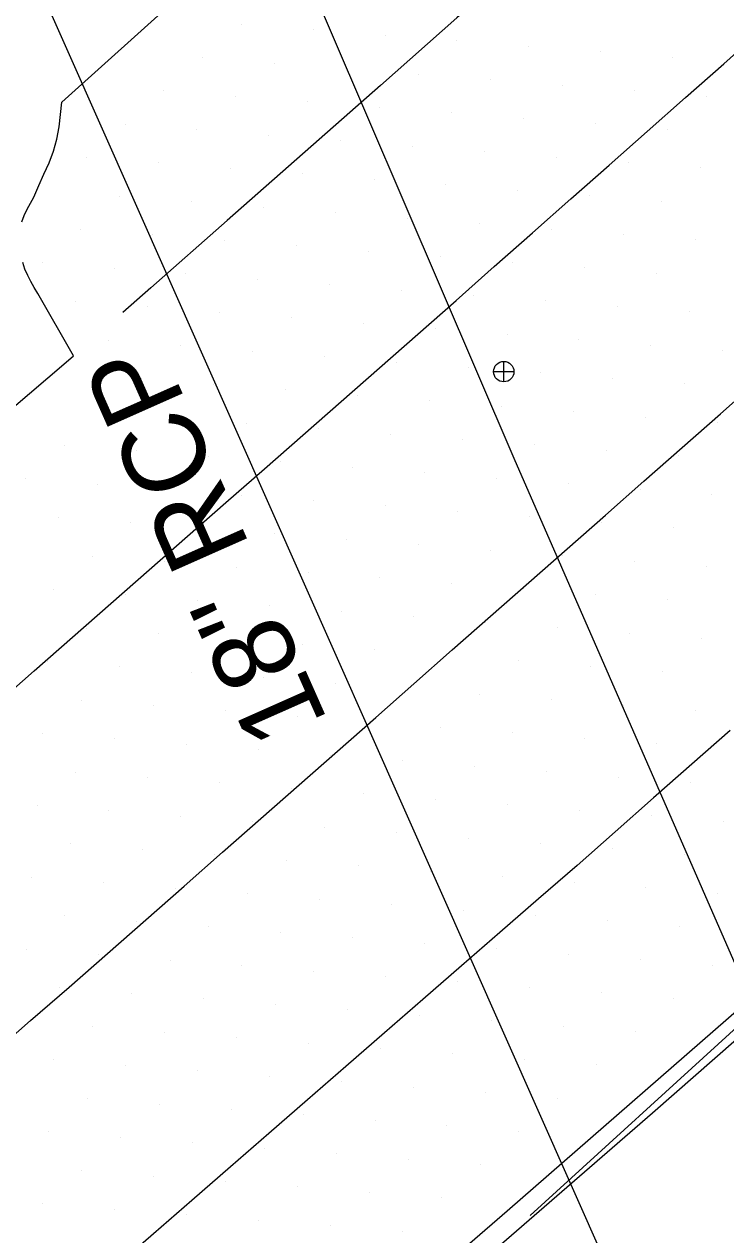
# Model space of a CAD drawing. Extents: x 1548934 to 1561348, y 809680 to 824075.
# Drawn here: x 1551806.2 to 1551840.5, y 810646.5 to 810705.8 of the extents above; entities that cross this region are included whole.
import ezdxf

# ---------------------------------------------------------------- set-up
doc = ezdxf.new("R2010")
doc.units = 0
for name, color, linetype in [('Default', 7, 'Continuous'), ('E_NCDOT_Vertical_Profile_Ground_Line', 7, 'Continuous'), ('Exist DTM Scan Elevation Point', 7, 'Continuous'), ('Exist Guardrail', 7, 'Continuous'), ('Exist Structure Major Deck Tunnel Box Culvert', 7, 'Continuous'), ('Exist Structure Minor Pipes RCP 18 Inch Size Material Text', 7, 'Continuous'), ('P_RDY_Terminator_Cell', 7, 'Continuous'), ('Pattern_8', 7, 'Continuous'), ('PH Exist DTM Breakline', 7, 'Continuous')]:
    doc.layers.add(name, color=color, linetype=linetype)

# ---------------------------------------------------------------- blocks, each defined once
blk = doc.blocks.new('SurveyPointCell')
at = {"layer": 'Default'}
for p, q in [((-0.5, 0), (0.5, 0)), ((0, -0.5), (0, 0.5))]:
    blk.add_line(p, q, dxfattribs=at)
blk.add_circle((0, 0), 0.5, dxfattribs=at)

msp = doc.modelspace()

# ---------------------------------------------------------------- linework, layer by layer
at = {"layer": 'E_NCDOT_Vertical_Profile_Ground_Line'}
for points in [[(1551761.526, 810588.983), (1551784.506, 810608.402), (1551807.145, 810628.085), (1551829.828, 810647.718), (1551842.707, 810658.962), (1551865.26, 810678.743), (1551887.773, 810698.643), (1551911.033, 810719.298)], [(1551806.048, 810696.165), (1551806.169, 810696.482), (1551806.314, 810696.789), (1551806.473, 810697.088), (1551806.639, 810697.383), (1551806.878, 810697.946), (1551807.132, 810698.502), (1551807.383, 810699.059), (1551807.604, 810699.627), (1551807.77, 810700.215), (1551807.879, 810700.816), (1551807.951, 810701.422), (1551808.004, 810702.031), (1551815.623, 810708.894)], [(1551785.404, 810669.822), (1551808.231, 810689.287), (1551808.584, 810689.599), (1551806.832, 810692.662), (1551806.658, 810692.949), (1551806.491, 810693.241), (1551806.338, 810693.541), (1551806.204, 810693.851), (1551806.093, 810694.17)]]:
    msp.add_lwpolyline(points, dxfattribs=at)
at = {"layer": 'Exist DTM Scan Elevation Point'}
for p, q in [((1551816.795, 810705.839), (1551816.795, 810705.839)), ((1551820.319, 810705.57), (1551820.319, 810705.57)), ((1551823.842, 810705.301), (1551823.842, 810705.301)), ((1551827.366, 810705.033), (1551827.366, 810705.033)), ((1551830.891, 810704.764), (1551830.891, 810704.764)), ((1551834.416, 810704.496), (1551834.416, 810704.496)), ((1551814.899, 810704.21), (1551814.899, 810704.21)), ((1551818.422, 810703.941), (1551818.422, 810703.941)), ((1551821.946, 810703.672), (1551821.946, 810703.672)), ((1551837.94, 810704.228), (1551837.94, 810704.228)), ((1551825.47, 810703.404), (1551825.47, 810703.404)), ((1551828.995, 810703.136), (1551828.995, 810703.136)), ((1551813.004, 810702.583), (1551813.004, 810702.583)), ((1551832.519, 810702.867), (1551832.519, 810702.867)), ((1551836.044, 810702.599), (1551836.044, 810702.599)), ((1551816.526, 810702.312), (1551816.526, 810702.312)), ((1551820.05, 810702.043), (1551820.05, 810702.043)), ((1551839.569, 810702.331), (1551839.569, 810702.331)), ((1551823.574, 810701.775), (1551823.574, 810701.775)), ((1551827.098, 810701.507), (1551827.098, 810701.507)), ((1551811.106, 810700.952), (1551811.106, 810700.952)), ((1551830.623, 810701.239), (1551830.623, 810701.239)), ((1551834.148, 810700.97), (1551834.148, 810700.97)), ((1551837.672, 810700.702), (1551837.672, 810700.702)), ((1551814.631, 810700.685), (1551814.631, 810700.685)), ((1551818.153, 810700.414), (1551818.153, 810700.414)), ((1551821.677, 810700.146), (1551821.677, 810700.146)), ((1551825.202, 810699.878), (1551825.202, 810699.878)), ((1551828.727, 810699.61), (1551828.727, 810699.61)), ((1551809.209, 810699.323), (1551809.209, 810699.323)), ((1551812.733, 810699.054), (1551812.733, 810699.054)), ((1551832.251, 810699.341), (1551832.251, 810699.341)), ((1551835.776, 810699.073), (1551835.776, 810699.073)), ((1551816.258, 810698.786), (1551816.258, 810698.786)), ((1551819.781, 810698.517), (1551819.781, 810698.517)), ((1551839.301, 810698.806), (1551839.301, 810698.806)), ((1551823.306, 810698.249), (1551823.306, 810698.249)), ((1551826.83, 810697.981), (1551826.83, 810697.981)), ((1551810.837, 810697.425), (1551810.837, 810697.425)), ((1551814.36, 810697.156), (1551814.36, 810697.156)), ((1551830.355, 810697.713), (1551830.355, 810697.713)), ((1551833.88, 810697.445), (1551833.88, 810697.445)), ((1551837.405, 810697.177), (1551837.405, 810697.177)), ((1551817.885, 810696.888), (1551817.885, 810696.888)), ((1551821.409, 810696.62), (1551821.409, 810696.62)), ((1551824.934, 810696.352), (1551824.934, 810696.352)), ((1551828.459, 810696.084), (1551828.459, 810696.084)), ((1551808.941, 810695.797), (1551808.941, 810695.797)), ((1551812.464, 810695.527), (1551812.464, 810695.527)), ((1551831.983, 810695.816), (1551831.983, 810695.816)), ((1551835.509, 810695.548), (1551835.509, 810695.548)), ((1551815.988, 810695.259), (1551815.988, 810695.259)), ((1551819.513, 810694.991), (1551819.513, 810694.991)), ((1551839.034, 810695.28), (1551839.034, 810695.28)), ((1551823.037, 810694.723), (1551823.037, 810694.723)), ((1551826.562, 810694.455), (1551826.562, 810694.455)), ((1551830.087, 810694.187), (1551830.087, 810694.187)), ((1551807.045, 810694.169), (1551807.045, 810694.169)), ((1551810.568, 810693.899), (1551810.568, 810693.899)), ((1551814.092, 810693.63), (1551814.092, 810693.63)), ((1551833.612, 810693.919), (1551833.612, 810693.919)), ((1551837.137, 810693.651), (1551837.137, 810693.651)), ((1551817.616, 810693.362), (1551817.616, 810693.362)), ((1551821.141, 810693.094), (1551821.141, 810693.094)), ((1551824.666, 810692.826), (1551824.666, 810692.826)), ((1551828.191, 810692.558), (1551828.191, 810692.558)), ((1551808.672, 810692.27), (1551808.672, 810692.27)), ((1551812.196, 810692.001), (1551812.196, 810692.001)), ((1551831.716, 810692.29), (1551831.716, 810692.29)), ((1551835.241, 810692.023), (1551835.241, 810692.023)), ((1551815.72, 810691.733), (1551815.72, 810691.733)), ((1551819.245, 810691.465), (1551819.245, 810691.465)), ((1551838.766, 810691.755), (1551838.766, 810691.755)), ((1551822.77, 810691.197), (1551822.77, 810691.197)), ((1551826.294, 810690.929), (1551826.294, 810690.929)), ((1551829.819, 810690.661), (1551829.819, 810690.661)), ((1551810.299, 810690.373), (1551810.299, 810690.373)), ((1551813.824, 810690.104), (1551813.824, 810690.104)), ((1551833.345, 810690.394), (1551833.345, 810690.394)), ((1551836.87, 810690.126), (1551836.87, 810690.126)), ((1551817.348, 810689.836), (1551817.348, 810689.836)), ((1551820.873, 810689.568), (1551820.873, 810689.568)), ((1551840.395, 810689.858), (1551840.395, 810689.858)), ((1551824.398, 810689.3), (1551824.398, 810689.3)), ((1551827.923, 810689.032), (1551827.923, 810689.032)), ((1551811.928, 810688.475), (1551811.928, 810688.475)), ((1551831.448, 810688.765), (1551831.448, 810688.765)), ((1551834.973, 810688.497), (1551834.973, 810688.497)), ((1551815.452, 810688.207), (1551815.452, 810688.207)), ((1551818.977, 810687.939), (1551818.977, 810687.939)), ((1551822.502, 810687.671), (1551822.502, 810687.671)), ((1551838.499, 810688.23), (1551838.499, 810688.23)), ((1551826.027, 810687.403), (1551826.027, 810687.403)), ((1551829.552, 810687.136), (1551829.552, 810687.136)), ((1551810.031, 810686.846), (1551810.031, 810686.846)), ((1551813.556, 810686.578), (1551813.556, 810686.578)), ((1551833.077, 810686.868), (1551833.077, 810686.868)), ((1551836.602, 810686.601), (1551836.602, 810686.601)), ((1551817.08, 810686.31), (1551817.08, 810686.31)), ((1551820.605, 810686.042), (1551820.605, 810686.042)), ((1551840.128, 810686.333), (1551840.128, 810686.333)), ((1551824.13, 810685.775), (1551824.13, 810685.775)), ((1551827.655, 810685.507), (1551827.655, 810685.507)), ((1551808.135, 810685.217), (1551808.135, 810685.217)), ((1551811.659, 810684.949), (1551811.659, 810684.949)), ((1551831.181, 810685.239), (1551831.181, 810685.239)), ((1551834.706, 810684.972), (1551834.706, 810684.972)), ((1551838.231, 810684.704), (1551838.231, 810684.704)), ((1551815.184, 810684.681), (1551815.184, 810684.681)), ((1551818.709, 810684.413), (1551818.709, 810684.413)), ((1551822.234, 810684.146), (1551822.234, 810684.146)), ((1551806.238, 810683.588), (1551806.238, 810683.588)), ((1551825.759, 810683.878), (1551825.759, 810683.878)), ((1551829.284, 810683.61), (1551829.284, 810683.61)), ((1551809.763, 810683.32), (1551809.763, 810683.32)), ((1551813.288, 810683.052), (1551813.288, 810683.052)), ((1551832.81, 810683.343), (1551832.81, 810683.343)), ((1551836.335, 810683.075), (1551836.335, 810683.075)), ((1551816.812, 810682.784), (1551816.812, 810682.784)), ((1551820.338, 810682.517), (1551820.338, 810682.517)), ((1551839.86, 810682.807), (1551839.86, 810682.807)), ((1551823.863, 810682.249), (1551823.863, 810682.249)), ((1551827.388, 810681.981), (1551827.388, 810681.981)), ((1551807.867, 810681.691), (1551807.867, 810681.691)), ((1551811.391, 810681.423), (1551811.391, 810681.423)), ((1551814.916, 810681.155), (1551814.916, 810681.155)), ((1551830.913, 810681.714), (1551830.913, 810681.714)), ((1551834.438, 810681.446), (1551834.438, 810681.446)), ((1551837.964, 810681.179), (1551837.964, 810681.179)), ((1551818.441, 810680.888), (1551818.441, 810680.888)), ((1551821.966, 810680.62), (1551821.966, 810680.62)), ((1551825.492, 810680.353), (1551825.492, 810680.353)), ((1551829.017, 810680.085), (1551829.017, 810680.085)), ((1551809.495, 810679.794), (1551809.495, 810679.794)), ((1551813.02, 810679.526), (1551813.02, 810679.526)), ((1551832.542, 810679.817), (1551832.542, 810679.817)), ((1551836.067, 810679.55), (1551836.067, 810679.55)), ((1551816.545, 810679.259), (1551816.545, 810679.259)), ((1551820.07, 810678.991), (1551820.07, 810678.991)), ((1551839.592, 810679.282), (1551839.592, 810679.282)), ((1551807.599, 810678.166), (1551807.599, 810678.166)), ((1551823.595, 810678.724), (1551823.595, 810678.724)), ((1551827.12, 810678.456), (1551827.12, 810678.456)), ((1551830.646, 810678.188), (1551830.646, 810678.188)), ((1551811.123, 810677.898), (1551811.123, 810677.898)), ((1551814.648, 810677.63), (1551814.648, 810677.63)), ((1551834.171, 810677.921), (1551834.171, 810677.921)), ((1551837.696, 810677.653), (1551837.696, 810677.653)), ((1551818.174, 810677.362), (1551818.174, 810677.362)), ((1551821.699, 810677.095), (1551821.699, 810677.095)), ((1551825.224, 810676.827), (1551825.224, 810676.827)), ((1551828.749, 810676.559), (1551828.749, 810676.559)), ((1551809.227, 810676.269), (1551809.227, 810676.269)), ((1551812.752, 810676.001), (1551812.752, 810676.001)), ((1551832.275, 810676.292), (1551832.275, 810676.292)), ((1551835.8, 810676.024), (1551835.8, 810676.024)), ((1551816.277, 810675.733), (1551816.277, 810675.733)), ((1551819.802, 810675.466), (1551819.802, 810675.466)), ((1551839.325, 810675.756), (1551839.325, 810675.756)), ((1551807.331, 810674.64), (1551807.331, 810674.64)), ((1551823.328, 810675.198), (1551823.328, 810675.198)), ((1551826.853, 810674.93), (1551826.853, 810674.93)), ((1551830.378, 810674.663), (1551830.378, 810674.663)), ((1551810.856, 810674.372), (1551810.856, 810674.372)), ((1551814.381, 810674.104), (1551814.381, 810674.104)), ((1551833.903, 810674.395), (1551833.903, 810674.395)), ((1551837.428, 810674.127), (1551837.428, 810674.127)), ((1551817.906, 810673.837), (1551817.906, 810673.837)), ((1551821.431, 810673.569), (1551821.431, 810673.569)), ((1551824.956, 810673.302), (1551824.956, 810673.302)), ((1551828.482, 810673.034), (1551828.482, 810673.034)), ((1551808.959, 810672.743), (1551808.959, 810672.743)), ((1551812.484, 810672.475), (1551812.484, 810672.475)), ((1551832.007, 810672.766), (1551832.007, 810672.766)), ((1551835.532, 810672.499), (1551835.532, 810672.499)), ((1551816.01, 810672.208), (1551816.01, 810672.208)), ((1551819.535, 810671.94), (1551819.535, 810671.94)), ((1551823.06, 810671.673), (1551823.06, 810671.673)), ((1551839.057, 810672.231), (1551839.057, 810672.231)), ((1551807.063, 810671.114), (1551807.063, 810671.114)), ((1551826.585, 810671.405), (1551826.585, 810671.405)), ((1551830.111, 810671.137), (1551830.111, 810671.137)), ((1551810.588, 810670.846), (1551810.588, 810670.846)), ((1551814.113, 810670.579), (1551814.113, 810670.579)), ((1551833.636, 810670.87), (1551833.636, 810670.87)), ((1551837.161, 810670.602), (1551837.161, 810670.602)), ((1551817.639, 810670.311), (1551817.639, 810670.311)), ((1551821.164, 810670.044), (1551821.164, 810670.044)), ((1551824.689, 810669.776), (1551824.689, 810669.776)), ((1551828.214, 810669.508), (1551828.214, 810669.508)), ((1551808.692, 810669.218), (1551808.692, 810669.218)), ((1551812.217, 810668.95), (1551812.217, 810668.95)), ((1551815.742, 810668.682), (1551815.742, 810668.682)), ((1551831.739, 810669.241), (1551831.739, 810669.241)), ((1551835.265, 810668.973), (1551835.265, 810668.973)), ((1551838.79, 810668.706), (1551838.79, 810668.706)), ((1551819.267, 810668.415), (1551819.267, 810668.415)), ((1551822.793, 810668.147), (1551822.793, 810668.147)), ((1551806.795, 810667.589), (1551806.795, 810667.589)), ((1551826.318, 810667.879), (1551826.318, 810667.879)), ((1551829.843, 810667.612), (1551829.843, 810667.612)), ((1551810.321, 810667.321), (1551810.321, 810667.321)), ((1551813.846, 810667.053), (1551813.846, 810667.053)), ((1551833.368, 810667.344), (1551833.368, 810667.344)), ((1551836.894, 810667.077), (1551836.894, 810667.077)), ((1551817.371, 810666.786), (1551817.371, 810666.786)), ((1551820.896, 810666.518), (1551820.896, 810666.518)), ((1551840.42, 810666.81), (1551840.42, 810666.81)), ((1551824.421, 810666.251), (1551824.421, 810666.251)), ((1551827.947, 810665.983), (1551827.947, 810665.983)), ((1551831.472, 810665.715), (1551831.472, 810665.715)), ((1551808.424, 810665.692), (1551808.424, 810665.692)), ((1551811.949, 810665.425), (1551811.949, 810665.425)), ((1551815.475, 810665.157), (1551815.475, 810665.157)), ((1551834.998, 810665.448), (1551834.998, 810665.448)), ((1551838.523, 810665.181), (1551838.523, 810665.181)), ((1551819, 810664.889), (1551819, 810664.889)), ((1551822.525, 810664.622), (1551822.525, 810664.622)), ((1551806.528, 810664.063), (1551806.528, 810664.063)), ((1551826.05, 810664.354), (1551826.05, 810664.354)), ((1551829.576, 810664.086), (1551829.576, 810664.086)), ((1551810.053, 810663.796), (1551810.053, 810663.796)), ((1551813.578, 810663.528), (1551813.578, 810663.528)), ((1551833.101, 810663.819), (1551833.101, 810663.819)), ((1551836.627, 810663.552), (1551836.627, 810663.552)), ((1551817.103, 810663.26), (1551817.103, 810663.26)), ((1551820.629, 810662.993), (1551820.629, 810662.993)), ((1551840.153, 810663.285), (1551840.153, 810663.285)), ((1551808.157, 810662.167), (1551808.157, 810662.167)), ((1551824.154, 810662.725), (1551824.154, 810662.725)), ((1551827.679, 810662.458), (1551827.679, 810662.458)), ((1551831.205, 810662.19), (1551831.205, 810662.19)), ((1551811.682, 810661.899), (1551811.682, 810661.899)), ((1551815.207, 810661.631), (1551815.207, 810661.631)), ((1551834.73, 810661.923), (1551834.73, 810661.923)), ((1551838.256, 810661.656), (1551838.256, 810661.656)), ((1551818.732, 810661.364), (1551818.732, 810661.364)), ((1551822.258, 810661.096), (1551822.258, 810661.096)), ((1551806.26, 810660.538), (1551806.26, 810660.538)), ((1551825.783, 810660.829), (1551825.783, 810660.829)), ((1551829.308, 810660.561), (1551829.308, 810660.561)), ((1551809.785, 810660.27), (1551809.785, 810660.27)), ((1551813.311, 810660.003), (1551813.311, 810660.003)), ((1551832.834, 810660.294), (1551832.834, 810660.294)), ((1551836.36, 810660.027), (1551836.36, 810660.027)), ((1551816.836, 810659.735), (1551816.836, 810659.735)), ((1551820.361, 810659.467), (1551820.361, 810659.467)), ((1551823.886, 810659.2), (1551823.886, 810659.2)), ((1551839.886, 810659.76), (1551839.886, 810659.76)), ((1551807.889, 810658.641), (1551807.889, 810658.641)), ((1551827.412, 810658.932), (1551827.412, 810658.932)), ((1551830.938, 810658.665), (1551830.938, 810658.665)), ((1551811.414, 810658.374), (1551811.414, 810658.374)), ((1551814.94, 810658.106), (1551814.94, 810658.106)), ((1551834.464, 810658.398), (1551834.464, 810658.398)), ((1551837.99, 810658.131), (1551837.99, 810658.131)), ((1551818.465, 810657.838), (1551818.465, 810657.838)), ((1551821.99, 810657.571), (1551821.99, 810657.571)), ((1551825.516, 810657.303), (1551825.516, 810657.303)), ((1551829.041, 810657.036), (1551829.041, 810657.036)), ((1551809.518, 810656.745), (1551809.518, 810656.745)), ((1551813.043, 810656.477), (1551813.043, 810656.477)), ((1551832.567, 810656.769), (1551832.567, 810656.769)), ((1551836.093, 810656.502), (1551836.093, 810656.502)), ((1551816.568, 810656.209), (1551816.568, 810656.209)), ((1551820.094, 810655.942), (1551820.094, 810655.942)), ((1551823.619, 810655.674), (1551823.619, 810655.674)), ((1551807.622, 810655.116), (1551807.622, 810655.116)), ((1551827.145, 810655.407), (1551827.145, 810655.407)), ((1551830.671, 810655.14), (1551830.671, 810655.14)), ((1551811.147, 810654.848), (1551811.147, 810654.848)), ((1551814.672, 810654.581), (1551814.672, 810654.581)), ((1551834.197, 810654.873), (1551834.197, 810654.873)), ((1551818.197, 810654.313), (1551818.197, 810654.313)), ((1551821.723, 810654.046), (1551821.723, 810654.046)), ((1551825.249, 810653.778), (1551825.249, 810653.778)), ((1551828.774, 810653.511), (1551828.774, 810653.511)), ((1551809.25, 810653.219), (1551809.25, 810653.219)), ((1551812.776, 810652.952), (1551812.776, 810652.952)), ((1551816.301, 810652.684), (1551816.301, 810652.684)), ((1551832.3, 810653.244), (1551832.3, 810653.244)), ((1551819.826, 810652.417), (1551819.826, 810652.417)), ((1551823.352, 810652.149), (1551823.352, 810652.149)), ((1551807.354, 810651.59), (1551807.354, 810651.59)), ((1551826.878, 810651.882), (1551826.878, 810651.882)), ((1551830.404, 810651.615), (1551830.404, 810651.615)), ((1551810.879, 810651.323), (1551810.879, 810651.323)), ((1551814.404, 810651.055), (1551814.404, 810651.055)), ((1551817.93, 810650.788), (1551817.93, 810650.788)), ((1551821.456, 810650.52), (1551821.456, 810650.52)), ((1551824.982, 810650.253), (1551824.982, 810650.253)), ((1551828.508, 810649.986), (1551828.508, 810649.986)), ((1551808.983, 810649.694), (1551808.983, 810649.694)), ((1551812.508, 810649.426), (1551812.508, 810649.426)), ((1551816.034, 810649.159), (1551816.034, 810649.159)), ((1551819.559, 810648.892), (1551819.559, 810648.892)), ((1551823.085, 810648.624), (1551823.085, 810648.624)), ((1551807.086, 810648.065), (1551807.086, 810648.065)), ((1551826.611, 810648.358), (1551826.611, 810648.358)), ((1551810.612, 810647.797), (1551810.612, 810647.797)), ((1551814.137, 810647.53), (1551814.137, 810647.53)), ((1551817.663, 810647.263), (1551817.663, 810647.263)), ((1551821.189, 810646.996), (1551821.189, 810646.996)), ((1551824.715, 810646.729), (1551824.715, 810646.729))]:
    msp.add_line(p, q, dxfattribs=at)
at = {"layer": 'Exist Guardrail'}
msp.add_lwpolyline([(1551904.412, 810712.079), (1551893.283, 810702.02), (1551882.055, 810692.075), (1551870.8, 810682.158), (1551859.512, 810672.281), (1551848.232, 810662.394), (1551836.949, 810652.511), (1551825.603, 810642.663)], dxfattribs=at)
at = {"layer": 'Exist Structure Major Deck Tunnel Box Culvert'}
msp.add_lwpolyline([(1551763.353, 810854.68), (1551776.069, 810819.842), (1551783.152, 810800.687), (1551795.344, 810769.157), (1551805.495, 810743.337), (1551817.592, 810713.867), (1551830.145, 810684.596), (1551846.388, 810647.478), (1551862.114, 810612.886), (1551864.95, 810606.898)], dxfattribs=at)
at = {"layer": 'P_RDY_Terminator_Cell'}
for points in [[(1551878.836, 810751.55), (1551876.115, 810749.151), (1551868.615, 810742.538), (1551864.865, 810739.231), (1551861.115, 810735.924), (1551857.365, 810732.617), (1551853.615, 810729.31), (1551849.865, 810726.003), (1551842.365, 810719.389), (1551838.615, 810716.082), (1551834.865, 810712.775), (1551831.115, 810709.468), (1551827.366, 810706.161), (1551823.616, 810702.854), (1551816.116, 810696.24), (1551812.366, 810692.933), (1551810.993, 810691.723)], [(1551804.778, 810672.529), (1551806.657, 810674.178), (1551808.536, 810675.827), (1551810.415, 810677.476), (1551812.294, 810679.125), (1551814.173, 810680.774), (1551816.052, 810682.423), (1551817.931, 810684.072), (1551819.811, 810685.721), (1551821.69, 810687.37), (1551823.569, 810689.019), (1551825.448, 810690.668), (1551827.324, 810692.32), (1551829.197, 810693.976), (1551831.07, 810695.632), (1551832.943, 810697.287), (1551834.816, 810698.943), (1551836.69, 810700.598), (1551838.563, 810702.254), (1551840.436, 810703.91), (1551842.309, 810705.565)], [(1551804.598, 810655.4), (1551806.483, 810657.042), (1551808.368, 810658.684), (1551810.252, 810660.328), (1551812.128, 810661.98), (1551814.004, 810663.632), (1551815.881, 810665.284), (1551817.757, 810666.936), (1551819.633, 810668.589), (1551821.51, 810670.241), (1551823.386, 810671.893), (1551825.262, 810673.545), (1551827.138, 810675.197), (1551829.015, 810676.849), (1551830.891, 810678.501), (1551832.767, 810680.153), (1551834.644, 810681.806), (1551836.52, 810683.458), (1551838.396, 810685.11), (1551840.273, 810686.762), (1551842.144, 810688.42)], [(1551840.748, 810671.255), (1551838.873, 810669.601), (1551836.998, 810667.947), (1551835.124, 810666.293), (1551833.248, 810664.64), (1551831.362, 810663), (1551829.475, 810661.359), (1551827.589, 810659.719), (1551825.702, 810658.078), (1551823.816, 810656.438), (1551821.929, 810654.797), (1551820.043, 810653.157), (1551818.156, 810651.516), (1551816.27, 810649.876), (1551814.384, 810648.235), (1551812.497, 810646.595), (1551810.611, 810644.954)]]:
    msp.add_lwpolyline(points, dxfattribs=at)
at = {"layer": 'Pattern_8'}
msp.add_lwpolyline([(1551772.004, 810786.253), (1551837.927, 810637.788)], dxfattribs=at)
at = {"layer": 'PH Exist DTM Breakline'}
msp.add_lwpolyline([(1551830.951, 810647.491), (1551841.446, 810657.057), (1551868.548, 810681.239)], dxfattribs=at)

# ---------------------------------------------------------------- block references
at = {"layer": 'Default'}
msp.add_blockref('SurveyPointCell', (1551829.66, 810688.829), dxfattribs=at)

# ---------------------------------------------------------------- texts
at = {"layer": 'Exist Structure Minor Pipes RCP 18 Inch Size Material Text'}
msp.add_text('18" RCP', height=4.02, rotation=113.94267, dxfattribs=at).set_placement((1551821.066, 810671.689))

doc.saveas('drawing.dxf')
